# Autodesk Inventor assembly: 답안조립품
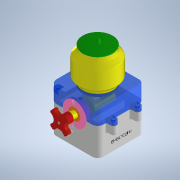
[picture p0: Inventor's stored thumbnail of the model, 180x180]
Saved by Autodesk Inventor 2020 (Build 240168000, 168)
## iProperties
Created: 2022-03
Part Number: 답안조립품
Document SubType Name: Assembly
Designer: Administrator
Author: Administrator
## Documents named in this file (11)
- C:\Users\Administrator\Desktop\박유정\답안조립품.iam
- C:\Users\Administrator\Desktop\박유정\본체.ipt
- C:\Users\Administrator\Desktop\박유정\본체커버.ipt
- C:\Users\Administrator\Desktop\박유정\핸들축.ipt
- C:\Users\Administrator\Desktop\박유정\앞커버.ipt
- C:\Users\Administrator\Desktop\박유정\베어링 부시.ipt
- C:\Users\Administrator\Desktop\박유정\용기.ipt
- C:\Users\Administrator\Desktop\박유정\볼트 M4x12.ipt
- C:\Users\Administrator\Desktop\박유정\핸들.ipt
- C:\Users\Administrator\Desktop\박유정\볼트 M3x12.ipt
- C:\Users\Administrator\Desktop\박유정\용기캡.ipt
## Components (2 placed, 2 different names)
1. 핸들축:1 — 각도:1
2. 핸들:1
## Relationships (1: Angle 1)
- 각도:1 [Angle]: 핸들축:1
